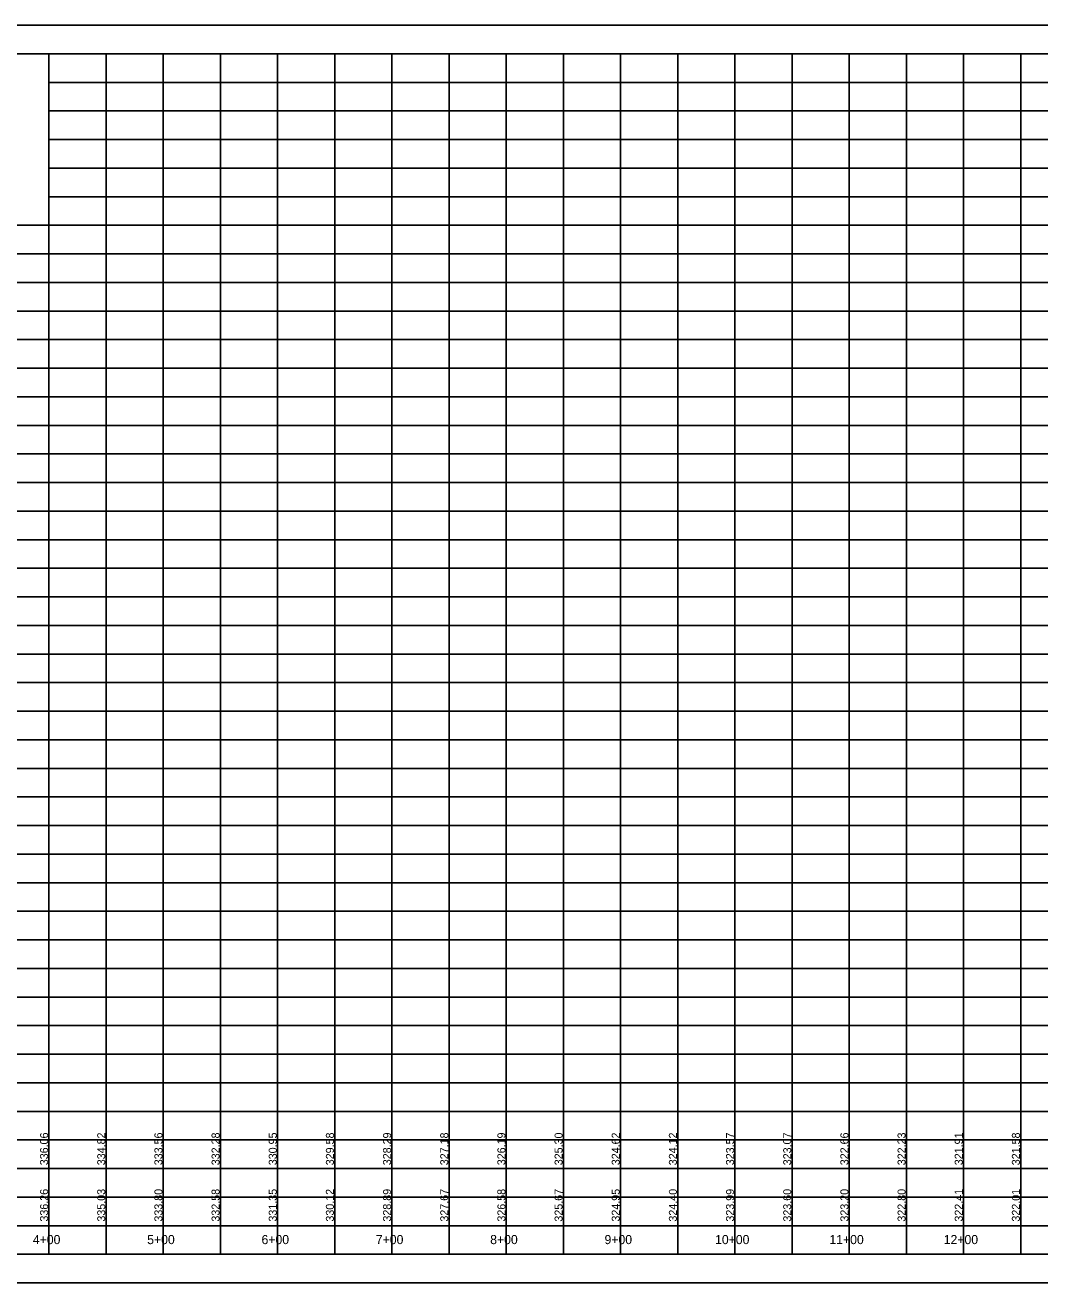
# Model space of a CAD drawing. Extents: x 1873632 to 1926512, y 813126 to 836257.
# Drawn here: x 1878742 to 1879630, y 831005 to 832105 of the extents above; entities that cross this region are included whole.
import ezdxf

# ---------------------------------------------------------------- set-up
doc = ezdxf.new("R2010")
doc.units = 0
for name, color, linetype in [('RD_DDB_StaTX', 7, 'Continuous'), ('RD_DDB_StripGrade', 7, 'Continuous'), ('RD_PD_WallFill', 7, 'Continuous'), ('RD_SHT_IplotShp', 7, 'Continuous')]:
    doc.layers.add(name, color=color, linetype=linetype)

msp = doc.modelspace()

# ---------------------------------------------------------------- linework, layer by layer
at = {"layer": 'RD_PD_WallFill'}
for p, q in [((1878312.8, 832079.5), (1883662.8, 832079.6)), ((1878312.8, 832079.5), (1880062.8, 832079.5)), ((1878362.8, 832079.5), (1880062.8, 832079.5)), ((1878762.8, 831029.5), (1878762.8, 832079.5)), ((1878812.8, 831029.5), (1878812.8, 832079.5)), ((1878862.8, 831029.5), (1878862.8, 832079.5)), ((1878912.8, 831029.5), (1878912.8, 832079.5)), ((1878962.8, 831029.5), (1878962.8, 832079.5)), ((1879012.8, 831029.5), (1879012.8, 832079.5)), ((1879062.8, 831029.5), (1879062.8, 832079.5)), ((1879112.8, 831029.5), (1879112.8, 832079.5)), ((1879162.8, 831029.5), (1879162.8, 832079.5)), ((1879212.8, 831029.5), (1879212.8, 832079.5)), ((1879262.8, 831029.5), (1879262.8, 832079.5)), ((1879312.8, 831029.5), (1879312.8, 832079.5)), ((1879362.8, 831029.5), (1879362.8, 832079.5)), ((1879412.8, 831029.5), (1879412.8, 832079.5)), ((1879462.8, 831029.5), (1879462.8, 832079.5)), ((1879512.8, 831029.5), (1879512.8, 832079.5)), ((1879562.8, 831029.5), (1879562.8, 832079.5)), ((1879612.8, 831029.5), (1879612.8, 832079.5)), ((1878762.8, 832054.5), (1883662.8, 832054.5)), ((1878762.8, 832029.5), (1883662.8, 832029.5)), ((1878762.8, 832004.5), (1883662.8, 832004.5)), ((1878762.8, 831979.5), (1883662.8, 831979.5)), ((1878762.8, 831954.5), (1883662.8, 831954.6)), ((1878312.8, 831929.5), (1883662.8, 831929.5)), ((1878312.8, 831904.5), (1883662.8, 831904.5)), ((1878312.8, 831879.5), (1883662.8, 831879.6)), ((1878312.8, 831854.5), (1883662.8, 831854.5)), ((1878312.8, 831829.5), (1883662.8, 831829.5)), ((1878312.8, 831804.5), (1883662.8, 831804.5)), ((1878312.8, 831779.5), (1883662.8, 831779.5)), ((1878312.8, 831754.5), (1883662.8, 831754.5)), ((1878312.8, 831729.5), (1883662.8, 831729.5)), ((1878312.8, 831704.5), (1883662.8, 831704.5)), ((1878312.8, 831679.5), (1883662.8, 831679.5)), ((1878312.8, 831654.5), (1883662.8, 831654.6)), ((1878312.8, 831629.5), (1883662.8, 831629.5)), ((1878312.8, 831604.5), (1883662.8, 831604.6)), ((1878312.8, 831579.5), (1883662.8, 831579.5)), ((1878312.8, 831554.5), (1883662.8, 831554.5)), ((1878312.8, 831529.5), (1883662.8, 831529.5)), ((1878312.8, 831504.5), (1883662.8, 831504.5)), ((1878312.8, 831479.5), (1883662.8, 831479.5)), ((1878312.8, 831454.5), (1883662.8, 831454.5)), ((1878312.8, 831429.5), (1883662.8, 831429.6)), ((1878312.8, 831404.5), (1883662.8, 831404.5)), ((1878312.8, 831379.5), (1883662.8, 831379.5)), ((1878312.8, 831354.5), (1883662.8, 831354.5)), ((1878312.8, 831329.5), (1883662.8, 831329.5)), ((1878312.8, 831304.5), (1883662.8, 831304.5)), ((1878312.8, 831279.5), (1883662.8, 831279.5)), ((1878312.8, 831254.5), (1883662.8, 831254.5)), ((1878312.8, 831229.5), (1883662.8, 831229.5)), ((1878312.8, 831204.5), (1883662.8, 831204.5)), ((1878312.8, 831179.5), (1883662.8, 831179.5)), ((1878312.8, 831154.5), (1883662.8, 831154.5)), ((1878312.8, 831129.5), (1883662.8, 831129.5)), ((1878312.8, 831104.5), (1883662.8, 831104.5)), ((1878312.8, 831079.5), (1883662.8, 831079.5)), ((1878362.8, 831054.5), (1883662.8, 831054.5)), ((1878312.8, 831029.5), (1883662.8, 831029.5))]:
    msp.add_line(p, q, dxfattribs=at)
msp.add_lwpolyline([(1878362.8, 832079.5), (1878762.8, 832079.5), (1878762.8, 831929.5), (1878362.8, 831929.5)], close=True, dxfattribs=at)
at = {"layer": 'RD_SHT_IplotShp'}
msp.add_lwpolyline([(1878287.8, 831004.5), (1883687.8, 831004.5), (1883687.8, 832104.5), (1878287.8, 832104.5)], close=True, dxfattribs=at)

# ---------------------------------------------------------------- texts
at = {"layer": 'RD_DDB_StaTX'}
for s, p in [('4+00', (1878748.8, 831038.4)), ('5+00', (1878848.8, 831038.4)), ('6+00', (1878948.8, 831038.4)), ('7+00', (1879048.8, 831038.4)), ('8+00', (1879148.8, 831038.4)), ('9+00', (1879248.8, 831038.4)), ('10+00', (1879345.5, 831038.4)), ('11+00', (1879445.5, 831038.4)), ('12+00', (1879545.5, 831038.4))]:
    msp.add_text(s, height=8, dxfattribs=at).set_placement(p)
at = {"layer": 'RD_DDB_StripGrade'}
for s, p in [('336.06', (1878762.1, 831107.4)), ('334.82', (1878812.1, 831107.4)), ('333.56', (1878862.1, 831107.4)), ('332.28', (1878912.1, 831107.4)), ('330.95', (1878962.1, 831107.4)), ('329.58', (1879012.1, 831107.4)), ('328.29', (1879062.1, 831107.4)), ('327.18', (1879112.1, 831107.4)), ('326.19', (1879162.1, 831107.4)), ('325.30', (1879212.1, 831107.4)), ('324.62', (1879262.1, 831107.4)), ('324.12', (1879312.1, 831107.4)), ('323.57', (1879362.1, 831107.4)), ('323.07', (1879412.1, 831107.4)), ('322.66', (1879462.1, 831107.4)), ('322.23', (1879512.1, 831107.4)), ('321.91', (1879562.1, 831107.4)), ('321.58', (1879612.1, 831107.4)), ('336.26', (1878762.1, 831058.1)), ('335.03', (1878812.1, 831058.1)), ('333.80', (1878862.1, 831058.1)), ('332.58', (1878912.1, 831058.1)), ('331.35', (1878962.1, 831058.1)), ('330.12', (1879012.1, 831058.1)), ('328.89', (1879062.1, 831058.1)), ('327.67', (1879112.1, 831058.1)), ('326.58', (1879162.1, 831058.1)), ('325.67', (1879212.1, 831058.1)), ('324.95', (1879262.1, 831058.1)), ('324.40', (1879312.1, 831058.1)), ('323.99', (1879362.1, 831058.1)), ('323.60', (1879412.1, 831058.1)), ('323.20', (1879462.1, 831058.1)), ('322.80', (1879512.1, 831058.1)), ('322.41', (1879562.1, 831058.1)), ('322.01', (1879612.1, 831058.1))]:
    msp.add_text(s, height=7, rotation=90, dxfattribs=at).set_placement(p)

doc.saveas('drawing.dxf')
